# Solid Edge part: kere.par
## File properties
Author: Georg
Template: Iso Part.par
Last saved by: kalle
Revision: 9
Application: Solid Edge
Accuracy: 0,990
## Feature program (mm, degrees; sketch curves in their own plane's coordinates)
sketch for "unnamed Protrusion 1" plane through (0, 0, 0) normal (1, 0, 0) x-axis (0, 1, 0)
  line (-13.5, -6.5) -> (13.5, -6.5)
  line (13.5, -6.5) -> (13.5, 6.5)
  line (13.5, 6.5) -> (7.5, 6.5)
  line (7.5, -3.5) -> (7.5, 6.5)
  line (-7.5, -3.5) -> (7.5, -3.5)
  line (-7.5, 6.5) -> (-7.5, -3.5)
  line (-7.5, 6.5) -> (-13.5, 6.5)
  line (-13.5, 6.5) -> (-13.5, -6.5)
  dimension (linear) = 13.5
  dimension (linear) = 7.5
  dimension (linear) = 7.5
  dimension (linear) = 7.5
  dimension (linear) = 13.5
  dimension (linear) = 13.5
  dimension (linear) = 13.5
extrude "unnamed Protrusion 1" add finite 130 along -normal
sketch for "ExtrudedCutout_1" #1 plane through (-65, -13.5, 6.5) normal (0, -1, 0) x-axis (1, 0, 0)
  circle centre (50, -6.5) radius 4
sketch for "ExtrudedCutout_1" #2 plane through (-65, -13.5, 6.5) normal (0, -1, 0) x-axis (1, 0, 0)
extrude "ExtrudedCutout_1" cut finite 55.1804 along -normal
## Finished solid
Body 1: solid body, 14 faces, 40 edges, 24 vertices.
  Faces by surface: plane 12, cylinder 2
  Edges by curve: line 32, circle 8
Bounding box of the edges (mm): 130.000 x 27.000 x 13.000, from (-130, -13.5, -6.5) to (0, 13.5, 6.5).
Cylindrical faces by radius (mm): R4 x2
Planar faces by outward normal: +x 1, +y 2, +z 5, -x 1, -y 2, -z 1
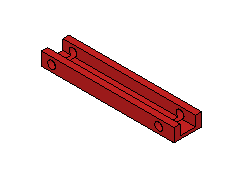
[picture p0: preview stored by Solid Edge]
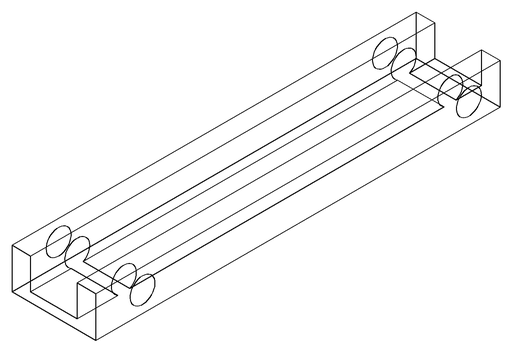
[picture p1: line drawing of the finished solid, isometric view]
